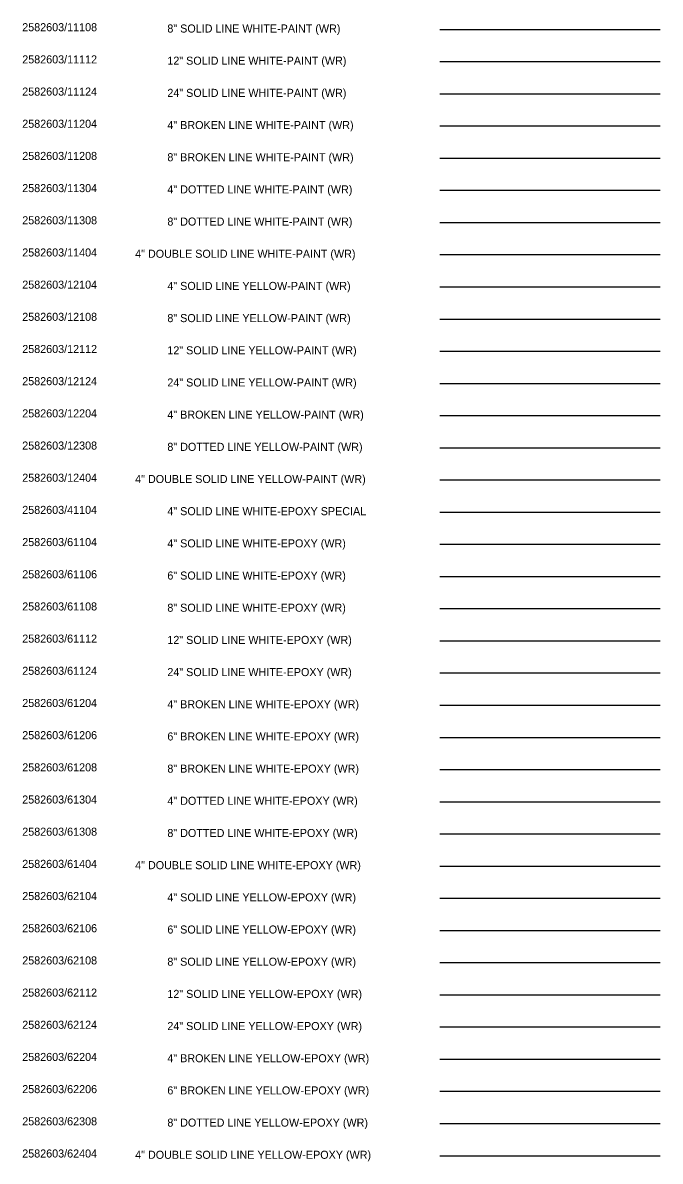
# Model space of a CAD drawing. Extents: x 2147712 to 2176316, y 2125036 to 2131746.
# Drawn here: x 2156196 to 2156790, y 2125727 to 2126788 of the extents above; entities that cross this region are included whole.
import ezdxf

# ---------------------------------------------------------------- set-up
doc = ezdxf.new("R2010")
doc.units = 0
doc.layers.add('DETAIL TXT', color=7, linetype='Continuous')
doc.layers.add('PVMT STRP', color=7, linetype='Continuous')

msp = doc.modelspace()

# ---------------------------------------------------------------- linework, layer by layer
at = {"layer": 'PVMT STRP'}
for p, q in [((2156584.7, 2126781.8), (2156790, 2126781.8)), ((2156584.7, 2126751.8), (2156790, 2126751.8)), ((2156584.7, 2126721.8), (2156790, 2126721.8)), ((2156584.7, 2126691.8), (2156790, 2126691.8)), ((2156584.7, 2126661.8), (2156790, 2126661.8)), ((2156584.7, 2126631.8), (2156790, 2126631.8)), ((2156584.7, 2126601.8), (2156790, 2126601.8)), ((2156584.7, 2126571.8), (2156790, 2126571.8)), ((2156584.7, 2126541.8), (2156790, 2126541.8)), ((2156584.7, 2126511.8), (2156790, 2126511.8)), ((2156584.7, 2126481.8), (2156790, 2126481.8)), ((2156584.7, 2126451.8), (2156790, 2126451.8)), ((2156584.7, 2126421.8), (2156790, 2126421.8)), ((2156584.7, 2126391.8), (2156790, 2126391.8)), ((2156584.7, 2126361.8), (2156790, 2126361.8)), ((2156584.7, 2126331.8), (2156790, 2126331.8)), ((2156584.7, 2126301.8), (2156790, 2126301.8)), ((2156584.7, 2126271.8), (2156790, 2126271.8)), ((2156584.7, 2126241.8), (2156790, 2126241.8)), ((2156584.7, 2126211.8), (2156790, 2126211.8)), ((2156584.7, 2126181.8), (2156790, 2126181.8)), ((2156584.7, 2126151.8), (2156790, 2126151.8)), ((2156584.7, 2126121.8), (2156790, 2126121.8)), ((2156584.7, 2126091.8), (2156790, 2126091.8)), ((2156584.7, 2126061.8), (2156790, 2126061.8)), ((2156584.7, 2126031.8), (2156790, 2126031.8)), ((2156584.7, 2126001.8), (2156790, 2126001.8)), ((2156584.7, 2125971.8), (2156790, 2125971.8)), ((2156584.7, 2125941.8), (2156790, 2125941.8)), ((2156584.7, 2125911.8), (2156790, 2125911.8)), ((2156584.7, 2125881.8), (2156790, 2125881.8)), ((2156584.7, 2125851.8), (2156790, 2125851.8)), ((2156584.7, 2125821.8), (2156790, 2125821.8)), ((2156584.7, 2125791.8), (2156790, 2125791.8)), ((2156584.7, 2125761.8), (2156790, 2125761.8)), ((2156584.7, 2125731.8), (2156790, 2125731.8))]:
    msp.add_line(p, q, dxfattribs=at)

# ---------------------------------------------------------------- texts
at = {"layer": 'DETAIL TXT'}
for s, p in [('2582603/11108', (2156195.6, 2126780.1)), ('8" SOLID LINE WHITE-PAINT (WR)', (2156330.8, 2126778.9)), ('2582603/11112', (2156195.6, 2126750.1)), ('12" SOLID LINE WHITE-PAINT (WR)', (2156330.8, 2126748.9)), ('2582603/11124', (2156195.6, 2126720.1)), ('24" SOLID LINE WHITE-PAINT (WR)', (2156330.8, 2126718.9)), ('2582603/11204', (2156195.6, 2126690.1)), ('4" BROKEN LINE WHITE-PAINT (WR)', (2156330.8, 2126688.9)), ('2582603/11208', (2156195.6, 2126660.1)), ('8" BROKEN LINE WHITE-PAINT (WR)', (2156330.8, 2126658.9)), ('2582603/11304', (2156195.6, 2126630.1)), ('4" DOTTED LINE WHITE-PAINT (WR)', (2156330.8, 2126628.9)), ('2582603/11308', (2156195.6, 2126600.1)), ('8" DOTTED LINE WHITE-PAINT (WR)', (2156330.8, 2126598.9)), ('2582603/11404', (2156195.6, 2126570.1)), ('4" DOUBLE SOLID LINE WHITE-PAINT (WR)', (2156300.8, 2126568.9)), ('2582603/12104', (2156195.6, 2126540.1)), ('4" SOLID LINE YELLOW-PAINT (WR)', (2156330.8, 2126538.9)), ('2582603/12108', (2156195.6, 2126510.1)), ('8" SOLID LINE YELLOW-PAINT (WR)', (2156330.8, 2126508.9)), ('2582603/12112', (2156195.6, 2126480.1)), ('12" SOLID LINE YELLOW-PAINT (WR)', (2156330.8, 2126478.9)), ('2582603/12124', (2156195.6, 2126450.1)), ('24" SOLID LINE YELLOW-PAINT (WR)', (2156330.8, 2126448.9)), ('2582603/12204', (2156195.6, 2126420.1)), ('4" BROKEN LINE YELLOW-PAINT (WR)', (2156330.8, 2126418.9)), ('2582603/12308', (2156195.6, 2126390.1)), ('8" DOTTED LINE YELLOW-PAINT (WR)', (2156330.8, 2126388.9)), ('2582603/12404', (2156195.6, 2126360.1)), ('4" DOUBLE SOLID LINE YELLOW-PAINT (WR)', (2156300.8, 2126358.9)), ('2582603/41104', (2156195.6, 2126330.1)), ('4" SOLID LINE WHITE-EPOXY SPECIAL', (2156330.8, 2126328.9)), ('2582603/61104', (2156195.6, 2126300.1)), ('4" SOLID LINE WHITE-EPOXY (WR)', (2156330.8, 2126298.9)), ('2582603/61106', (2156195.6, 2126270.1)), ('6" SOLID LINE WHITE-EPOXY (WR)', (2156330.8, 2126268.9)), ('2582603/61108', (2156195.6, 2126240.1)), ('8" SOLID LINE WHITE-EPOXY (WR)', (2156330.8, 2126238.9)), ('2582603/61112', (2156195.6, 2126210.1)), ('12" SOLID LINE WHITE-EPOXY (WR)', (2156330.8, 2126208.9)), ('2582603/61124', (2156195.6, 2126180.1)), ('24" SOLID LINE WHITE-EPOXY (WR)', (2156330.8, 2126178.9)), ('2582603/61204', (2156195.6, 2126150.1)), ('4" BROKEN LINE WHITE-EPOXY (WR)', (2156330.8, 2126148.9)), ('2582603/61206', (2156195.6, 2126120.1)), ('6" BROKEN LINE WHITE-EPOXY (WR)', (2156330.8, 2126118.9)), ('2582603/61208', (2156195.6, 2126090.1)), ('8" BROKEN LINE WHITE-EPOXY (WR)', (2156330.8, 2126088.9)), ('2582603/61304', (2156195.6, 2126060.1)), ('4" DOTTED LINE WHITE-EPOXY (WR)', (2156330.8, 2126058.9)), ('2582603/61308', (2156195.6, 2126030.1)), ('8" DOTTED LINE WHITE-EPOXY (WR)', (2156330.8, 2126028.9)), ('2582603/61404', (2156195.6, 2126000.1)), ('4" DOUBLE SOLID LINE WHITE-EPOXY (WR)', (2156300.8, 2125998.9)), ('2582603/62104', (2156195.6, 2125970.1)), ('4" SOLID LINE YELLOW-EPOXY (WR)', (2156330.8, 2125968.9)), ('2582603/62106', (2156195.6, 2125940.1)), ('6" SOLID LINE YELLOW-EPOXY (WR)', (2156330.8, 2125938.9)), ('2582603/62108', (2156195.6, 2125910.1)), ('8" SOLID LINE YELLOW-EPOXY (WR)', (2156330.8, 2125908.9)), ('2582603/62112', (2156195.6, 2125880.1)), ('12" SOLID LINE YELLOW-EPOXY (WR)', (2156330.8, 2125878.9)), ('2582603/62124', (2156195.6, 2125850.1)), ('24" SOLID LINE YELLOW-EPOXY (WR)', (2156330.8, 2125848.9)), ('2582603/62204', (2156195.6, 2125820.1)), ('4" BROKEN LINE YELLOW-EPOXY (WR)', (2156330.8, 2125818.9)), ('2582603/62206', (2156195.6, 2125790.1)), ('6" BROKEN LINE YELLOW-EPOXY (WR)', (2156330.8, 2125788.9)), ('2582603/62308', (2156195.6, 2125760.1)), ('8" DOTTED LINE YELLOW-EPOXY (WR)', (2156330.8, 2125758.9)), ('2582603/62404', (2156195.6, 2125730.1)), ('4" DOUBLE SOLID LINE YELLOW-EPOXY (WR)', (2156300.8, 2125728.9))]:
    msp.add_text(s, height=7.5, dxfattribs=at).set_placement(p)

doc.saveas('drawing.dxf')
